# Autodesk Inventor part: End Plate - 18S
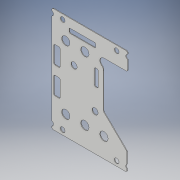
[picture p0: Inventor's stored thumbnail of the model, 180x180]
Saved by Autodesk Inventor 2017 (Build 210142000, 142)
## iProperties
Created: 2021-03
Part Number: End Plate - 18S
Material: Generic
Document SubType Name: Modeling
Designer: Win240
Density: 1 g/cm^3
Appearance: Default
Author: Win240
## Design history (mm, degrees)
sketch "Sketch1"
  geometry: L1 (0, 0)-(119, 0); L2 (119, 0)-(119, -27.5); L3 (119, -165)-(0, -165); L4 (0, -165)-(0, 0); L5 (-1, -7.5)-(120, -7.5); L6 (120, -7.5)-(120, -157.5); L7 (120, -157.5)-(-1, -157.5); L8 (-1, -157.5)-(-1, -7.5); L9 (-1, -7.5)-(0, -3.886); L10 (120, -7.5)-(119, -3.886); L11 (59.5, -7.5)-(59.5, 0); L12 (59.5, -157.5)-(59.5, -165); L13 (22, -34)-(52, -34); L14 (52, -34)-(82, -34); L15 (82, -34)-(82, -134); L16 (82, -134)-(52, -134); L17 (52, -134)-(22, -134); L18 (22, -134)-(22, -34); L19 (67, -47.5)-(73, -47.5); L20 (73, -47.5)-(73, -73.5); L21 (73, -73.5)-(67, -73.5); L22 (67, -73.5)-(67, -47.5); L23 (82, -27.5)-(119, -27.5); L24 (81, -44.618)-(81, -92.5); L25 (48, -107)-(68, -107); L26 (35, -61)-(81, -61); L27 (81, -92.5)-(91, -92.5); L28 (91, -92.5)-(91, -110.5); L29 (91, -110.5)-(119, -110.5); L30 (119, -27.5)-(119, -110.5); L31 (119, -110.5)-(119, -165); L32 (102, -7.5)-(102, -157.5); L33 (102, -7.5)-(119, -3.886); L34 (17, -7.5)-(0, -3.886); L35 (17, -157.5)-(17, -7.5); C1 r 6.5 at (22, -34); C2 r 6.5 at (52, -34); C3 r 6.5 at (82, -134); C4 r 6.5 at (52, -134); C5 r 6.5 at (22, -134); C6 r 4.75 at (68, -107); C7 r 4.75 at (35, -61); C8 r 3.75 at (102, -7.5); C9 r 4.75 at (48, -107); C10 r 3.75 at (102, -157.5); C11 r 3.75 at (17, -7.5); C12 r 3.75 at (17, -157.5); A1 r 3.75 centre (-1, -7.5) between (0, -11.114) and (0, -3.886); A2 r 3.75 centre (120, -7.5) between (119, -3.886) and (119, -11.114); A3 r 3.75 centre (120, -157.5) between (119, -153.886) and (119, -161.114); A4 r 3.75 centre (-1, -157.5) between (0, -161.114) and (0, -153.886); A5 r 6.5 centre (82, -34) between (82, -27.5) and (78.25, -39.309); A6 r 4.75 centre (81, -61) between (81, -56.25) and (81, -65.75); A7 r 6.5 centre (74.5, -44.618) between (81, -44.618) and (78.25, -39.309); A8 r 6.5 centre (82, -34) between (82, -40.5) and (82, -27.5); A9 r 6.5 centre (82, -34) between (78.25, -39.309) and (82, -40.5); A10 r 4.75 centre (81, -61) between (82, -56.356) and (81, -56.25); A11 r 4.75 centre (81, -61) between (82, -65.644) and (82, -56.356); A12 r 4.75 centre (81, -61) between (81, -65.75) and (82, -65.644)
  constraints: 70 end point, 24 centre point, 24 point on circle, 22 point on line, 16 equal radius, 13 horizontal, 9 vertical, 6 parallel, 4 equal length, 4 midpoint, 4 perpendicular, 4 tangent
  dimensions: "d0" = 119 distance of L3.start L3.end; "d1" = 165 distance of L1.end L3.start; "d2" = 150 distance of L5.end L6.end; "d3" = 121 distance of L6.end L7.end; "d4" = 3.75 radius of A1; "d5" = 13 diameter of C1; "d6" = 30 distance of L13.start L13.end; "d7" = 100 distance of L17.end L13.start; "d8" = 26.5 distance between parallel lines of L5 L13; "d9" = 23 distance between parallel lines of L18 L8; "d10" = 9.5 diameter of C7; "d11" = 36 distance from line of L26.start L8; "d12" = 69 distance from line of L25.end L8; "d13" = 53.5 distance from line of L26.start L5; "d14" = 99.5 distance from line of L5 L25.end; "d15" = 103 distance of L32.start L5.start; "d16" = 66 distance between parallel lines of L21 L5; "d17" = 40 distance between parallel lines of L19 L5; "d18" = 68 distance between parallel lines of L22 L8; "d19" = 74 distance between parallel lines of L20 L8; "d20" = 82 distance between parallel lines of L8 L24; "d21" = 82 distance from line of L8 L26.end; "d22" = 49 distance from line of L25.start L8; "d23" = 85 distance between parallel lines of L5 L27; "d24" = 92 distance between parallel lines of L8 L28; "d25" = 103 distance between parallel lines of L5 L29
extrude "Mechanical Holes" new body sketch "Sketch1" distance "d26" = 1; taper "d27" = 0 deg
sketch "Sketch2"
  geometry: L1 (0, -11.114)-(0, -153.886) reference; L2 (119, 0)-(0, 0) reference; L3 (0, -165)-(119, -165) reference; L4 (69, -13.5)-(27, -13.5); L5 (27, -13.5)-(27, -20.5); L6 (27, -20.5)-(69, -20.5); L7 (69, -20.5)-(69, -13.5); L8 (3, -47.5)-(13, -47.5); L9 (13, -47.5)-(13, -75.5); L10 (13, -75.5)-(3, -75.5); L11 (3, -75.5)-(3, -47.5); L12 (13, -89.5)-(3, -89.5); L13 (3, -89.5)-(3, -117.5); L14 (3, -117.5)-(13, -117.5); L15 (13, -117.5)-(13, -89.5); A1 r 3.75 centre (-1, -7.5) between (0, -11.114) and (0, -3.886) reference
  constraints: 24 end point, 6 parallel, 3 collinear, 3 horizontal, 3 perpendicular
  dimensions: "d28" = 4 distance from line of L11 A1.centre; "d29" = 10 distance of L8.start L8.end; "d30" = 68 distance from line of L10 A1.centre; "d31" = 82 distance from line of L12 A1.centre; "d32" = 28 distance of L8.end L9.end; "d33" = 6 distance from line of A1.centre L4; "d34" = 13 distance from line of A1.centre L6; "d35" = 28 distance from line of L5 A1.centre; "d36" = 70 distance from line of A1.centre L7
extrude "Air Holes" cut sketch "Sketch2" stored distance "d37" = 1; taper "d38" = 0 deg
sketch "Sketch4"
  geometry: L1 (-119, -153.886)-(-119, -110.5) reference; L2 (-119, -165)-(-119, -161.114) reference; L3 (-118, -136.721)-(-118, -154.328); L4 (-118, -160.672)-(-118, -165); L5 (-118, -165)-(-119, -165); L6 (-119, -110.5)-(-91, -110.5) reference; L7 (-118, -136.721)-(-91, -110.5); L8 (-68, -107)-(-120, -157.5); L9 (-91, -110.5)-(-81, -100.788); L10 (-91, -110.5)-(-91, -92.5) reference; L11 (-91, -92.5)-(-81, -92.5) reference; L12 (-81, -92.5)-(-81, -100.788); C1 r 4.75 at (-68, -107) reference; A1 r 3.75 centre (-120, -157.5) between (-119, -161.114) and (-119, -153.886) reference; 1 further point
  constraints: 14 end point, 3 vertical, 2 collinear, 2 point on circle, 1 horizontal, 1 parallel
  dimensions: "d41" = 1 distance of L4.end L2.start
extrude "Increase Airflow Below Connector" cut sketch "Sketch4" stored distance "d42" = 10; taper "d43" = 0 deg
fillet "Fillet1" dims "d39" = 2
body "Solid1"
